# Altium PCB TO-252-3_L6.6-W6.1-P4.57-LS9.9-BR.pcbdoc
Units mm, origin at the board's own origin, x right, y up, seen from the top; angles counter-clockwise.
Board outline 24.14 x 19.33 mm, 2 copper layers (Top Layer, Bottom Layer), stack 0 mm thick; 1 components, 0 nets, 3 pads, 0 vias.
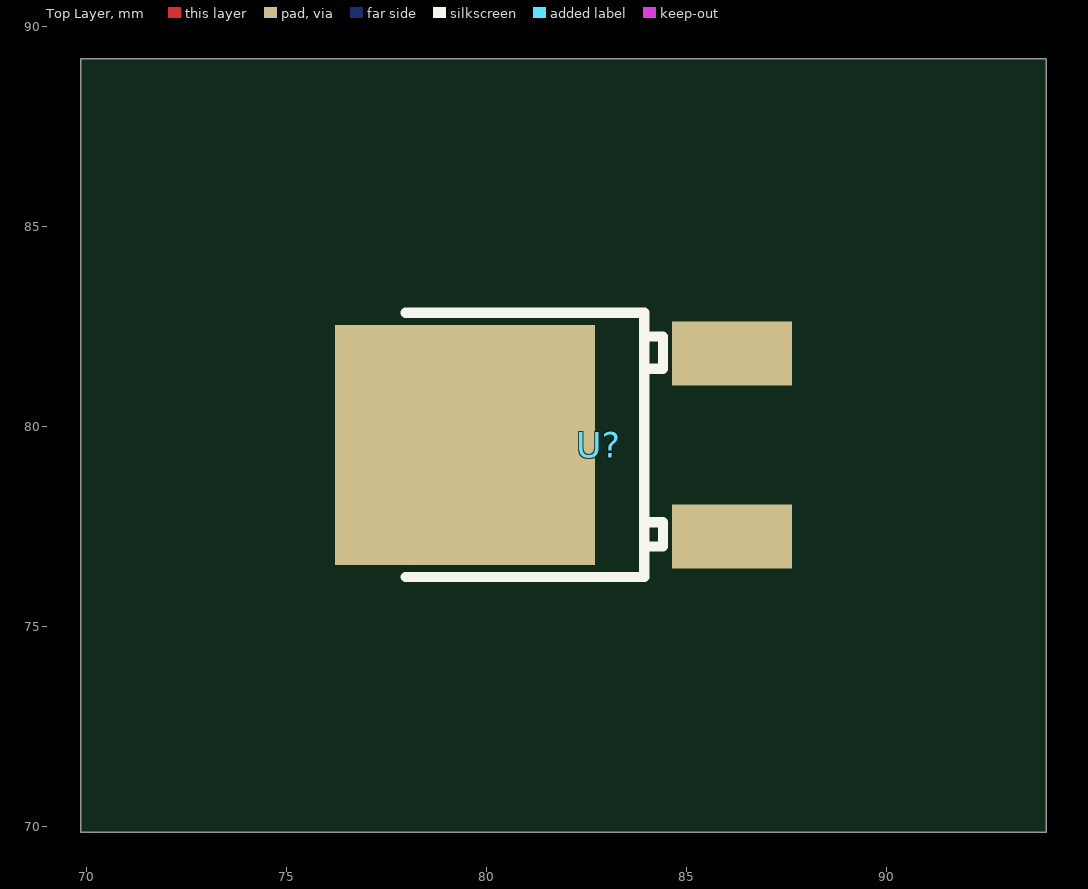
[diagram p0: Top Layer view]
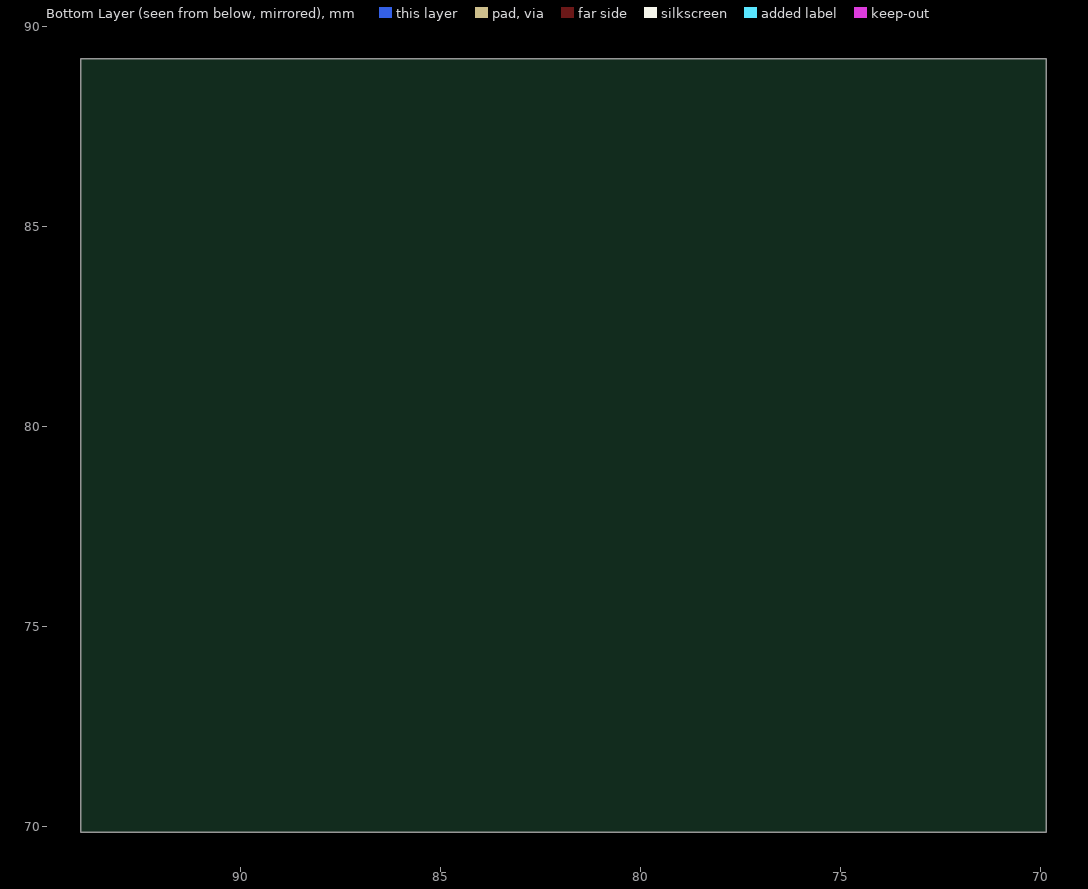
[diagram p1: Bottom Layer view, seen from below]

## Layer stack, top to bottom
Top Layer: signal copper (thickness not stored)
Bottom Layer: signal copper (thickness not stored)

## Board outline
93.985,69.85 69.85,69.85 69.85,89.182 93.985,89.182

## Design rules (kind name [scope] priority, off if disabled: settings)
PasteMaskExpansion "Paste Mask Expansion" [All] p1: expansion=0
SolderMaskExpansion "Solder Mask Expansion" [IsVia] p1: expansion=-25.4 istentingtop=TRUE
SolderMaskExpansion "Solder Mask Expansion" [All] p2: expansion=0.051 istentingtop=FALSE

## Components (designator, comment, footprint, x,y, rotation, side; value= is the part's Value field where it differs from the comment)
U? "" TO-252-3_L6.6-W6.1-P4.57-LS9.9-BR 82.793,79.53 r0 top

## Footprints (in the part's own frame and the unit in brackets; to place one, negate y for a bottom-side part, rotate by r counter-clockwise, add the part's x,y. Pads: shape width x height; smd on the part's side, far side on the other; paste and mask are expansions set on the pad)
TO-252-3_L6.6-W6.1-P4.57-LS9.9-BR [mm]
  rect 3x1.6 smd: 1(3.343,-2.285) 2(3.343,2.285)
  rect 6.5x6 smd: 3(-3.343,0)
  silkscreen extent -4.83,-3.3 1.61,3.3

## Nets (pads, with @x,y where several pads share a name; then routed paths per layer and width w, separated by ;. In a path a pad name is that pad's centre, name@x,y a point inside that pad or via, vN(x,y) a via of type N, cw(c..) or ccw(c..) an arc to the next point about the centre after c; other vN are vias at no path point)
pads on no net: U?.1 U?.2 U?.3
